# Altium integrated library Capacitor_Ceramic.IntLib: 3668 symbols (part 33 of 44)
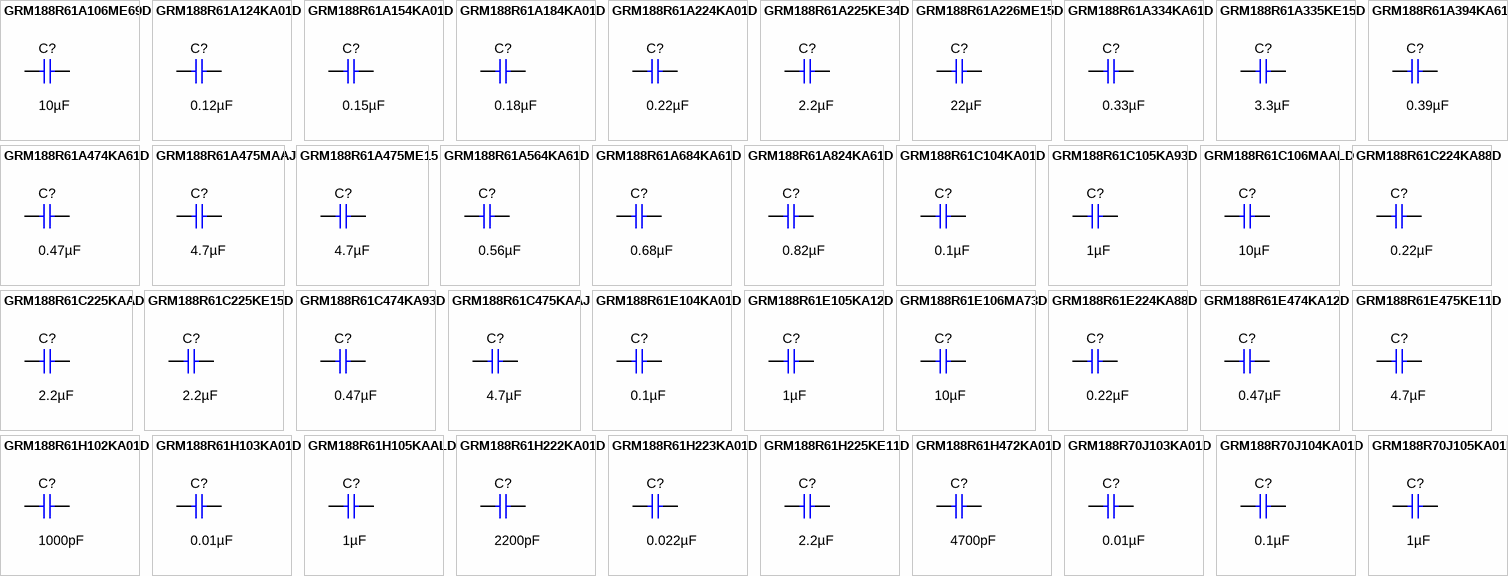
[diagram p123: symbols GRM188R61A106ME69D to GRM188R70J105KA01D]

## GRM188R61A224KA01D
designator C?  ValueDisplayed: 0.22µF  (hidden comment: GRM188R61A224KA01D)
CAP, CERM, 0.22 µF, 10 V,+/- 10%, X5R, 0603; Manufacturer: MuRata; Polarized: N; CompType: Capacitor; Value: 0.22uF; U/M: EA; Cap_F: 0.00000022; Tolerance_%: 10; Value2: 10V; TaMin_C: -55; TaMax_C: 85; Cap_Case: 0603; SizeArea_mm2: 1.28; SizeAreaWB_mm2: 4.68; SizeX_mm: 1.6; SizeY_mm: 0.8; SizeZ_mm: 1; AEC Category: Q200; Green_Lifecycle: Active; Green_REACh: Passed
signal-integrity model Cap
simulation model Cap
footprint 0603
footprint 0603M
footprint 0603L
footprint 0603_HV
footprint 0603S
pins: 1, 2

## GRM188R61A225KE34D
designator C?  ValueDisplayed: 2.2µF  (hidden comment: GRM188R61A225KE34D)
CAP, CERM, 2.2 µF, 10 V,+/- 10%, X5R, 0603; Manufacturer: MuRata; Polarized: N; CompType: Capacitor; Value: 2.2uF; U/M: EA; Cap_F: 0.0000022; Tolerance_%: 10; Value2: 10V; TaMin_C: -55; TaMax_C: 85; Cap_Case: 0603; SizeArea_mm2: 1.28; SizeAreaWB_mm2: 4.68; SizeX_mm: 1.6; SizeY_mm: 0.8; SizeZ_mm: 1; AEC Category: Q200; Green_Lifecycle: Active; Green_REACh: Passed
signal-integrity model Cap
simulation model Cap
footprint 0603
footprint 0603M
footprint 0603L
footprint 0603_HV
footprint 0603S
pins: 1, 2

## GRM188R61A226ME15D
designator C?  ValueDisplayed: 22µF  (hidden comment: GRM188R61A226ME15D)
CAP, CERM, 22 µF, 10 V,+/- 20%, X5R, 0603; Manufacturer: MuRata; Polarized: N; CompType: Capacitor; Value: 22uF; U/M: EA; Cap_F: 0.000022; Tolerance_%: 20; VDC_V: 10; Value2: 10V; TaMin_C: -55; TaMax_C: 85; Cap_Case: 0603; SizeArea_mm2: 1.28; SizeAreaWB_mm2: 4.68; SizeX_mm: 1.6; SizeY_mm: 0.8; SizeZ_mm: 1; AEC Category: Q200; Green_Lifecycle: Active; Green_REACh: Passed
signal-integrity model Cap
simulation model Cap
footprint 0603
footprint 0603M
footprint 0603L
footprint 0603_HV
footprint 0603S
pins: 1, 2

## GRM188R61A334KA61D
designator C?  ValueDisplayed: 0.33µF  (hidden comment: GRM188R61A334KA61D)
CAP, CERM, 0.33 µF, 10 V,+/- 10%, X5R, 0603; Manufacturer: MuRata; Polarized: N; CompType: Capacitor; Value: 0.33uF; U/M: EA; Cap_F: 0.00000033; Tolerance_%: 10; Value2: 10V; TaMin_C: -55; TaMax_C: 85; Cap_Case: 0603; SizeArea_mm2: 1.28; SizeAreaWB_mm2: 4.68; SizeX_mm: 1.6; SizeY_mm: 0.8; SizeZ_mm: 1; AEC Category: Q200
signal-integrity model Cap
simulation model Cap
footprint 0603
footprint 0603M
footprint 0603L
footprint 0603_HV
footprint 0603S
pins: 1, 2

## GRM188R61A335KE15D
designator C?  ValueDisplayed: 3.3µF  (hidden comment: GRM188R61A335KE15D)
CAP, CERM, 3.3 µF, 10 V,+/- 10%, X5R, 0603; Manufacturer: MuRata; Polarized: N; CompType: Capacitor; Value: 3.3uF; U/M: EA; Cap_F: 0.0000033; Tolerance_%: 10; ESR_ohm: 0.005; Value1: 0.005 ohm; Value2: 10V; IRMS_A: 1.7; TaMin_C: -55; TaMax_C: 85; Cap_Case: 0603; SizeArea_mm2: 1.28; SizeAreaWB_mm2: 4.68; SizeX_mm: 1.6; SizeY_mm: 0.8; SizeZ_mm: 1; AEC Category: Q200
signal-integrity model Cap
simulation model Cap
footprint 0603
footprint 0603M
footprint 0603L
footprint 0603_HV
footprint 0603S
pins: 1, 2

## GRM188R61A394KA61D
designator C?  ValueDisplayed: 0.39µF  (hidden comment: GRM188R61A394KA61D)
CAP, CERM, 0.39 µF, 10 V,+/- 10%, X5R, 0603; Manufacturer: MuRata; Polarized: N; CompType: Capacitor; Value: 0.39uF; U/M: EA; Cap_F: 0.00000039; Tolerance_%: 10; Value2: 10V; TaMin_C: -55; TaMax_C: 85; Cap_Case: 0603; SizeArea_mm2: 1.28; SizeAreaWB_mm2: 4.68; SizeX_mm: 1.6; SizeY_mm: 0.8; SizeZ_mm: 1; AEC Category: Q200
signal-integrity model Cap
simulation model Cap
footprint 0603
footprint 0603M
footprint 0603L
footprint 0603_HV
footprint 0603S
pins: 1, 2

## GRM188R61A474KA61D
designator C?  ValueDisplayed: 0.47µF  (hidden comment: GRM188R61A474KA61D)
CAP, CERM, 0.47 µF, 10 V,+/- 10%, X5R, 0603; Manufacturer: MuRata; Polarized: N; CompType: Capacitor; Value: 0.47uF; U/M: EA; Cap_F: 0.00000047; Tolerance_%: 10; Value2: 10V; TaMin_C: -55; TaMax_C: 85; Cap_Case: 0603; SizeArea_mm2: 1.28; SizeAreaWB_mm2: 4.68; SizeX_mm: 1.6; SizeY_mm: 0.8; SizeZ_mm: 1; AEC Category: Q200; Green_Lifecycle: Active; Green_REACh: Passed
signal-integrity model Cap
simulation model Cap
footprint 0603
footprint 0603M
footprint 0603L
footprint 0603_HV
footprint 0603S
pins: 1, 2

## GRM188R61A475MAAJ
designator C?  ValueDisplayed: 4.7µF  (hidden comment: GRM188R61A475MAAJ)
CAP, CERM, 4.7 µF, 10 V,+/- 20%, X5R, 0603; Manufacturer: MuRata; Polarized: N; CompType: Capacitor; Value: 4.7uF; U/M: EA; Cap_F: 0.0000047; Tolerance_%: 20; VDC_V: 10; Value2: 10V; TaMin_C: -55; TaMax_C: 85; Cap_Case: 0603; SizeArea_mm2: 1.28; SizeAreaWB_mm2: 4.68; SizeX_mm: 1.6; SizeY_mm: 0.8; SizeZ_mm: 1; AEC Category: Q200
signal-integrity model Cap
simulation model Cap
footprint 0603
footprint 0603M
footprint 0603L
footprint 0603_HV
footprint 0603S
pins: 1, 2

## GRM188R61A475ME15
designator C?  ValueDisplayed: 4.7µF  (hidden comment: GRM188R61A475ME15)
CAP, CERM, 4.7 µF, 10 V,+/- 20%, X5R, 0603; Manufacturer: MuRata; Polarized: N; CompType: Capacitor; Value: 4.7uF; U/M: EA; Cap_F: 0.0000047; Tolerance_%: 20; VDC_V: 10; Value2: 10V; TaMin_C: -55; TaMax_C: 85; Cap_Case: 0603; SizeArea_mm2: 1.28; SizeAreaWB_mm2: 4.68; SizeX_mm: 1.6; SizeY_mm: 0.8; SizeZ_mm: 1; AEC Category: Q200; Green_Lifecycle: Active; Green_REACh: Passed
signal-integrity model Cap
simulation model Cap
footprint 0603
footprint 0603M
footprint 0603L
footprint 0603_HV
footprint 0603S
pins: 1, 2

## GRM188R61A564KA61D
designator C?  ValueDisplayed: 0.56µF  (hidden comment: GRM188R61A564KA61D)
CAP, CERM, 0.56 µF, 10 V,+/- 10%, X5R, 0603; Manufacturer: MuRata; Polarized: N; CompType: Capacitor; Value: 0.56uF; U/M: EA; Cap_F: 0.00000056; Tolerance_%: 10; Value2: 10V; TaMin_C: -55; TaMax_C: 85; Cap_Case: 0603; SizeArea_mm2: 1.28; SizeAreaWB_mm2: 4.68; SizeX_mm: 1.6; SizeY_mm: 0.8; SizeZ_mm: 1; AEC Category: Q200
signal-integrity model Cap
simulation model Cap
footprint 0603
footprint 0603M
footprint 0603L
footprint 0603_HV
footprint 0603S
pins: 1, 2

## GRM188R61A684KA61D
designator C?  ValueDisplayed: 0.68µF  (hidden comment: GRM188R61A684KA61D)
CAP, CERM, 0.68 µF, 10 V,+/- 10%, X5R, 0603; Manufacturer: MuRata; Polarized: N; CompType: Capacitor; Value: 0.68uF; U/M: EA; Cap_F: 0.00000068; Tolerance_%: 10; Value2: 10V; TaMin_C: -55; TaMax_C: 85; Cap_Case: 0603; SizeArea_mm2: 1.28; SizeAreaWB_mm2: 4.68; SizeX_mm: 1.6; SizeY_mm: 0.8; SizeZ_mm: 1; AEC Category: Q200; Green_Lifecycle: Active; Green_REACh: Passed
signal-integrity model Cap
simulation model Cap
footprint 0603
footprint 0603M
footprint 0603L
footprint 0603_HV
footprint 0603S
pins: 1, 2

## GRM188R61A824KA61D
designator C?  ValueDisplayed: 0.82µF  (hidden comment: GRM188R61A824KA61D)
CAP, CERM, 0.82 µF, 10 V,+/- 10%, X5R, 0603; Manufacturer: MuRata; Polarized: N; CompType: Capacitor; Value: 0.82uF; U/M: EA; Cap_F: 0.00000082; Tolerance_%: 10; Value2: 10V; TaMin_C: -55; TaMax_C: 85; Cap_Case: 0603; SizeArea_mm2: 1.28; SizeAreaWB_mm2: 4.68; SizeX_mm: 1.6; SizeY_mm: 0.8; SizeZ_mm: 1; AEC Category: Q200
signal-integrity model Cap
simulation model Cap
footprint 0603
footprint 0603M
footprint 0603L
footprint 0603_HV
footprint 0603S
pins: 1, 2

## GRM188R61C104KA01D
designator C?  ValueDisplayed: 0.1µF  (hidden comment: GRM188R61C104KA01D)
CAP, CERM, 0.1 µF, 16 V,+/- 10%, X5R, 0603; Manufacturer: MuRata; Polarized: N; CompType: Capacitor; Value: 0.1uF; U/M: EA; Cap_F: 0.0000001; Tolerance_%: 10; VDC_V: 16; Value2: 16V; TaMin_C: -55; TaMax_C: 85; Cap_Case: 0603; SizeArea_mm2: 1.28; SizeAreaWB_mm2: 4.68; SizeX_mm: 1.6; SizeY_mm: 0.8; SizeZ_mm: 1; AEC Category: Q200; Green_Lifecycle: Active; Green_REACh: Passed
signal-integrity model Cap
simulation model Cap
footprint 0603
footprint 0603M
footprint 0603L
footprint 0603_HV
footprint 0603S
pins: 1, 2

## GRM188R61C105KA93D
designator C?  ValueDisplayed: 1µF  (hidden comment: GRM188R61C105KA93D)
CAP, CERM, 1 µF, 16 V,+/- 10%, X5R, 0603; Manufacturer: MuRata; Polarized: N; CompType: Capacitor; Value: 1uF; U/M: EA; Cap_F: 0.000001; Tolerance_%: 10; VDC_V: 16; Value2: 16V; TaMin_C: -55; TaMax_C: 85; Cap_Case: 0603; SizeArea_mm2: 1.28; SizeAreaWB_mm2: 4.68; SizeX_mm: 1.6; SizeY_mm: 0.8; SizeZ_mm: 1; AEC Category: Q200; Green_Lifecycle: Active; Green_REACh: Passed
signal-integrity model Cap
simulation model Cap
footprint 0603
footprint 0603M
footprint 0603L
footprint 0603_HV
footprint 0603S
pins: 1, 2

## GRM188R61C106MAALD
designator C?  ValueDisplayed: 10µF  (hidden comment: GRM188R61C106MAALD)
CAP, CERM, 10 µF, 16 V,+/- 20%, X5R, 0603; Manufacturer: MuRata; Polarized: N; CompType: Capacitor; Value: 10uF; U/M: EA; Cap_F: 0.00001; Tolerance_%: 20; VDC_V: 16; Value2: 16V; TaMin_C: -55; TaMax_C: 85; Cap_Case: 0603; SizeArea_mm2: 1.28; SizeAreaWB_mm2: 4.68; SizeX_mm: 1.6; SizeY_mm: 0.8; SizeZ_mm: 1; AEC Category: Q200; Green_Lifecycle: Active; Green_REACh: Passed
signal-integrity model Cap
simulation model Cap
footprint 0603
footprint 0603M
footprint 0603L
footprint 0603_HV
footprint 0603S
pins: 1, 2

## GRM188R61C224KA88D
designator C?  ValueDisplayed: 0.22µF  (hidden comment: GRM188R61C224KA88D)
CAP, CERM, 0.22 µF, 16 V,+/- 10%, X5R, 0603; Manufacturer: MuRata; Polarized: N; CompType: Capacitor; Value: 0.22uF; U/M: EA; Cap_F: 0.00000022; Tolerance_%: 10; VDC_V: 16; Value2: 16V; TaMin_C: -55; TaMax_C: 85; Cap_Case: 0603; SizeArea_mm2: 1.28; SizeAreaWB_mm2: 4.68; SizeX_mm: 1.6; SizeY_mm: 0.8; SizeZ_mm: 1; AEC Category: Q200; Green_Lifecycle: Active; Green_REACh: Passed
signal-integrity model Cap
simulation model Cap
footprint 0603
footprint 0603M
footprint 0603L
footprint 0603_HV
footprint 0603S
pins: 1, 2

## GRM188R61C225KAAD
designator C?  ValueDisplayed: 2.2µF  (hidden comment: GRM188R61C225KAAD)
CAP, CERM, 2.2 µF, 16 V,+/- 10%, X5R, 0603; Manufacturer: MuRata; Polarized: N; CompType: Capacitor; Value: 2.2uF; U/M: EA; Cap_F: 0.0000022; Tolerance_%: 10; VDC_V: 16; Value2: 16V; TaMin_C: -55; TaMax_C: 85; Cap_Case: 0603; SizeArea_mm2: 1.28; SizeAreaWB_mm2: 4.68; SizeX_mm: 1.6; SizeY_mm: 0.8; SizeZ_mm: 1; AEC Category: Q200; Green_Lifecycle: Not Set; Green_REACh: Incomplete
signal-integrity model Cap
simulation model Cap
footprint 0603
footprint 0603M
footprint 0603L
footprint 0603_HV
footprint 0603S
pins: 1, 2

## GRM188R61C225KE15D
designator C?  ValueDisplayed: 2.2µF  (hidden comment: GRM188R61C225KE15D)
CAP, CERM, 2.2 µF, 16 V,+/- 10%, X5R, 0603; Manufacturer: MuRata; Polarized: N; CompType: Capacitor; Value: 2.2uF; U/M: EA; Cap_F: 0.0000022; Tolerance_%: 10; VDC_V: 16; Value2: 16V; TaMin_C: -55; TaMax_C: 85; Cap_Case: 0603; SizeArea_mm2: 1.28; SizeAreaWB_mm2: 4.68; SizeX_mm: 1.6; SizeY_mm: 0.8; SizeZ_mm: 1; AEC Category: Q200; Green_Lifecycle: Active; Green_REACh: Passed
signal-integrity model Cap
simulation model Cap
footprint 0603
footprint 0603M
footprint 0603L
footprint 0603_HV
footprint 0603S
pins: 1, 2

## GRM188R61C474KA93D
designator C?  ValueDisplayed: 0.47µF  (hidden comment: GRM188R61C474KA93D)
CAP, CERM, 0.47 µF, 16 V,+/- 10%, X5R, 0603; Manufacturer: MuRata; Polarized: N; CompType: Capacitor; Value: 0.47uF; U/M: EA; Cap_F: 0.00000047; Tolerance_%: 10; VDC_V: 16; Value2: 16V; TaMin_C: -55; TaMax_C: 85; Cap_Case: 0603; SizeArea_mm2: 1.28; SizeAreaWB_mm2: 4.68; SizeX_mm: 1.6; SizeY_mm: 0.8; SizeZ_mm: 1; AEC Category: Q200; Green_Lifecycle: Active; Green_REACh: Passed
signal-integrity model Cap
simulation model Cap
footprint 0603
footprint 0603M
footprint 0603L
footprint 0603_HV
footprint 0603S
pins: 1, 2

## GRM188R61C475KAAJ
designator C?  ValueDisplayed: 4.7µF  (hidden comment: GRM188R61C475KAAJ)
CAP, CERM, 4.7 µF, 16 V,+/- 10%, X5R, 0603; Manufacturer: MuRata; Polarized: N; CompType: Capacitor; Value: 4.7uF; U/M: EA; Cap_F: 0.0000047; Tolerance_%: 10; VDC_V: 16; Value2: 16V; TaMin_C: -55; TaMax_C: 85; Cap_Case: 0603; SizeArea_mm2: 1.28; SizeAreaWB_mm2: 4.68; SizeX_mm: 1.6; SizeY_mm: 0.8; SizeZ_mm: 1; AEC Category: Q200; Green_Lifecycle: Active; Green_REACh: Passed
signal-integrity model Cap
simulation model Cap
footprint 0603
footprint 0603M
footprint 0603L
footprint 0603_HV
footprint 0603S
pins: 1, 2

## GRM188R61E104KA01D
designator C?  ValueDisplayed: 0.1µF  (hidden comment: GRM188R61E104KA01D)
CAP, CERM, 0.1 µF, 25 V,+/- 10%, X5R, 0603; Manufacturer: MuRata; Polarized: N; CompType: Capacitor; Value: 0.1uF; U/M: EA; Cap_F: 0.0000001; Tolerance_%: 10; VDC_V: 25; Value2: 25V; TaMin_C: -55; TaMax_C: 85; Cap_Case: 0603; SizeArea_mm2: 1.28; SizeAreaWB_mm2: 4.68; SizeX_mm: 1.6; SizeY_mm: 0.8; SizeZ_mm: 1; AEC Category: Q200; Green_Lifecycle: Active; Green_REACh: Passed
signal-integrity model Cap
simulation model Cap
footprint 0603
footprint 0603M
footprint 0603L
footprint 0603_HV
footprint 0603S
pins: 1, 2

## GRM188R61E105KA12D
designator C?  ValueDisplayed: 1µF  (hidden comment: GRM188R61E105KA12D)
CAP, CERM, 1 µF, 25 V,+/- 10%, X5R, 0603; Manufacturer: MuRata; Polarized: N; CompType: Capacitor; Value: 1uF; U/M: EA; Cap_F: 0.000001; Tolerance_%: 10; VDC_V: 25; Value2: 25V; TaMin_C: -55; TaMax_C: 85; Cap_Case: 0603; SizeArea_mm2: 1.28; SizeAreaWB_mm2: 4.68; SizeX_mm: 1.6; SizeY_mm: 0.8; SizeZ_mm: 1; AEC Category: Q200; Green_Lifecycle: Active; Green_REACh: Passed
signal-integrity model Cap
simulation model Cap
footprint 0603
footprint 0603M
footprint 0603L
footprint 0603_HV
footprint 0603S
pins: 1, 2

## GRM188R61E106MA73D
designator C?  ValueDisplayed: 10µF  (hidden comment: GRM188R61E106MA73D)
CAP, CERM, 10 µF, 25 V,+/- 20%, X5R, 0603; Manufacturer: MuRata; Polarized: N; CompType: Capacitor; Value: 10uF; U/M: EA; Cap_F: 0.00001; Tolerance_%: 20; VDC_V: 25; Value2: 25V; TaMin_C: -55; TaMax_C: 85; Cap_Case: 0603; SizeArea_mm2: 1.28; SizeAreaWB_mm2: 4.68; SizeX_mm: 1.6; SizeY_mm: 0.8; SizeZ_mm: 1; AEC Category: Q200; Green_Lifecycle: Active; Green_REACh: Passed
signal-integrity model Cap
simulation model Cap
footprint 0603
footprint 0603M
footprint 0603L
footprint 0603_HV
footprint 0603S
pins: 1, 2

## GRM188R61E224KA88D
designator C?  ValueDisplayed: 0.22µF  (hidden comment: GRM188R61E224KA88D)
CAP, CERM, 0.22 µF, 25 V,+/- 10%, X5R, 0603; Manufacturer: MuRata; Polarized: N; CompType: Capacitor; Value: 0.22uF; U/M: EA; Cap_F: 0.00000022; Tolerance_%: 10; VDC_V: 25; Value2: 25V; TaMin_C: -55; TaMax_C: 85; Cap_Case: 0603; SizeArea_mm2: 1.28; SizeAreaWB_mm2: 4.68; SizeX_mm: 1.6; SizeY_mm: 0.8; SizeZ_mm: 1; AEC Category: Q200; Green_Lifecycle: Active; Green_REACh: Passed
signal-integrity model Cap
simulation model Cap
footprint 0603
footprint 0603M
footprint 0603L
footprint 0603_HV
footprint 0603S
pins: 1, 2

## GRM188R61E474KA12D
designator C?  ValueDisplayed: 0.47µF  (hidden comment: GRM188R61E474KA12D)
CAP, CERM, 0.47 µF, 25 V,+/- 10%, X5R, 0603; Manufacturer: MuRata; Polarized: N; CompType: Capacitor; Value: 0.47uF; U/M: EA; Cap_F: 0.00000047; Tolerance_%: 10; VDC_V: 25; Value2: 25V; TaMin_C: -55; TaMax_C: 85; Cap_Case: 0603; SizeArea_mm2: 1.28; SizeAreaWB_mm2: 4.68; SizeX_mm: 1.6; SizeY_mm: 0.8; SizeZ_mm: 1; AEC Category: Q200; Green_Lifecycle: Active; Green_REACh: Passed
signal-integrity model Cap
simulation model Cap
footprint 0603
footprint 0603M
footprint 0603L
footprint 0603_HV
footprint 0603S
pins: 1, 2

## GRM188R61E475KE11D
designator C?  ValueDisplayed: 4.7µF  (hidden comment: GRM188R61E475KE11D)
CAP, CERM, 4.7 µF, 25 V,+/- 10%, X5R, 0603; Manufacturer: MuRata; Polarized: N; CompType: Capacitor; Value: 4.7uF; U/M: EA; Cap_F: 0.0000047; Tolerance_%: 10; VDC_V: 25; Value2: 25V; TaMin_C: -55; TaMax_C: 85; Cap_Case: 0603; SizeArea_mm2: 1.28; SizeAreaWB_mm2: 4.68; SizeX_mm: 1.6; SizeY_mm: 0.8; SizeZ_mm: 1; AEC Category: Q200; Green_Lifecycle: Active; Green_REACh: Passed
signal-integrity model Cap
simulation model Cap
footprint 0603
footprint 0603M
footprint 0603L
footprint 0603_HV
footprint 0603S
pins: 1, 2

## GRM188R61H102KA01D
designator C?  ValueDisplayed: 1000pF  (hidden comment: GRM188R61H102KA01D)
CAP, CERM, 1000 pF, 50 V,+/- 10%, X5R, 0603; Manufacturer: MuRata; Polarized: N; CompType: Capacitor; Value: 1000pF; U/M: EA; Cap_F: 0.000000001; Tolerance_%: 10; VDC_V: 50; Value2: 50V; TaMin_C: -55; TaMax_C: 85; Cap_Case: 0603; SizeArea_mm2: 1.28; SizeAreaWB_mm2: 4.68; SizeX_mm: 1.6; SizeY_mm: 0.8; SizeZ_mm: 1; AEC Category: Q200; Green_Lifecycle: Active; Green_REACh: Passed
signal-integrity model Cap
simulation model Cap
footprint 0603
footprint 0603M
footprint 0603L
footprint 0603_HV
footprint 0603S
pins: 1, 2

## GRM188R61H103KA01D
designator C?  ValueDisplayed: 0.01µF  (hidden comment: GRM188R61H103KA01D)
CAP, CERM, 0.01 µF, 50 V,+/- 10%, X5R, 0603; Manufacturer: MuRata; Polarized: N; CompType: Capacitor; Value: 0.01uF; U/M: EA; Cap_F: 0.00000001; Tolerance_%: 10; VDC_V: 50; Value2: 50V; TaMin_C: -55; TaMax_C: 85; Cap_Case: 0603; SizeArea_mm2: 1.28; SizeAreaWB_mm2: 4.68; SizeX_mm: 1.6; SizeY_mm: 0.8; SizeZ_mm: 1; AEC Category: Q200; Green_Lifecycle: Active; Green_REACh: Passed
signal-integrity model Cap
simulation model Cap
footprint 0603
footprint 0603M
footprint 0603L
footprint 0603_HV
footprint 0603S
pins: 1, 2

## GRM188R61H105KAALD
designator C?  ValueDisplayed: 1µF  (hidden comment: GRM188R61H105KAALD)
CAP, CERM, 1 µF, 50 V,+/- 10%, X5R, 0603; Manufacturer: MuRata; Polarized: N; CompType: Capacitor; Value: 1uF; U/M: EA; Cap_F: 0.000001; Tolerance_%: 10; VDC_V: 50; Value2: 50V; TaMin_C: -55; TaMax_C: 85; Cap_Case: 0603; SizeArea_mm2: 1.28; SizeAreaWB_mm2: 4.68; SizeX_mm: 1.6; SizeY_mm: 0.8; SizeZ_mm: 1; AEC Category: Q200; Green_Lifecycle: Active; Green_REACh: Passed
signal-integrity model Cap
simulation model Cap
footprint 0603
footprint 0603M
footprint 0603L
footprint 0603_HV
footprint 0603S
pins: 1, 2

## GRM188R61H222KA01D
designator C?  ValueDisplayed: 2200pF  (hidden comment: GRM188R61H222KA01D)
CAP, CERM, 2200 pF, 50 V,+/- 10%, X5R, 0603; Manufacturer: MuRata; Polarized: N; CompType: Capacitor; Value: 2200pF; U/M: EA; Cap_F: 0.0000000022; Tolerance_%: 10; VDC_V: 50; Value2: 50V; TaMin_C: -55; TaMax_C: 85; Cap_Case: 0603; SizeArea_mm2: 1.28; SizeAreaWB_mm2: 4.68; SizeX_mm: 1.6; SizeY_mm: 0.8; SizeZ_mm: 1; AEC Category: Q200
signal-integrity model Cap
simulation model Cap
footprint 0603
footprint 0603M
footprint 0603L
footprint 0603_HV
footprint 0603S
pins: 1, 2

## GRM188R61H223KA01D
designator C?  ValueDisplayed: 0.022µF  (hidden comment: GRM188R61H223KA01D)
CAP, CERM, 0.022 µF, 50 V,+/- 10%, X5R, 0603; Manufacturer: MuRata; Polarized: N; CompType: Capacitor; Value: 0.022uF; U/M: EA; Cap_F: 0.000000022; Tolerance_%: 10; VDC_V: 50; Value2: 50V; TaMin_C: -55; TaMax_C: 85; Cap_Case: 0603; SizeArea_mm2: 1.28; SizeAreaWB_mm2: 4.68; SizeX_mm: 1.6; SizeY_mm: 0.8; SizeZ_mm: 1; AEC Category: Q200
signal-integrity model Cap
simulation model Cap
footprint 0603
footprint 0603M
footprint 0603L
footprint 0603_HV
footprint 0603S
pins: 1, 2

## GRM188R61H225KE11D
designator C?  ValueDisplayed: 2.2µF  (hidden comment: GRM188R61H225KE11D)
CAP, CERM, 2.2 µF, 50 V,+/- 10%, X5R, 0603; Manufacturer: MuRata; Polarized: N; CompType: Capacitor; Value: 2.2uF; U/M: EA; Cap_F: 0.0000022; Tolerance_%: 10; VDC_V: 50; Value2: 50V; TaMin_C: -55; TaMax_C: 85; Cap_Case: 0603; SizeArea_mm2: 1.28; SizeAreaWB_mm2: 4.68; SizeX_mm: 1.6; SizeY_mm: 0.8; SizeZ_mm: 1; AEC Category: Q200
signal-integrity model Cap
simulation model Cap
footprint 0603
footprint 0603M
footprint 0603L
footprint 0603_HV
footprint 0603S
pins: 1, 2

## GRM188R61H472KA01D
designator C?  ValueDisplayed: 4700pF  (hidden comment: GRM188R61H472KA01D)
CAP, CERM, 4700 pF, 50 V,+/- 10%, X5R, 0603; Manufacturer: MuRata; Polarized: N; CompType: Capacitor; Value: 4700pF; U/M: EA; Cap_F: 0.0000000047; Tolerance_%: 10; VDC_V: 50; Value2: 50V; TaMin_C: -55; TaMax_C: 85; Cap_Case: 0603; SizeArea_mm2: 1.28; SizeAreaWB_mm2: 4.68; SizeX_mm: 1.6; SizeY_mm: 0.8; SizeZ_mm: 1; AEC Category: Q200; Green_Lifecycle: Active; Green_REACh: Passed
signal-integrity model Cap
simulation model Cap
footprint 0603
footprint 0603M
footprint 0603L
footprint 0603_HV
footprint 0603S
pins: 1, 2

## GRM188R70J103KA01D
designator C?  ValueDisplayed: 0.01µF  (hidden comment: GRM188R70J103KA01D)
CAP, CERM, 0.01 µF, 6.3 V,+/- 10%, X7R, 0603; Manufacturer: MuRata; Polarized: N; CompType: Capacitor; Value: 0.01uF; U/M: EA; Cap_F: 0.00000001; Tolerance_%: 10; VDC_V: 6.3; Value2: 6.3V; TaMin_C: -55; TaMax_C: 125; Cap_Case: 0603; SizeArea_mm2: 1.28; SizeAreaWB_mm2: 4.68; SizeX_mm: 1.6; SizeY_mm: 0.8; SizeZ_mm: 1; AEC Category: Q200; Green_Lifecycle: Active; Green_REACh: Passed
signal-integrity model Cap
simulation model Cap
footprint 0603
footprint 0603M
footprint 0603L
footprint 0603_HV
footprint 0603S
pins: 1, 2

## GRM188R70J104KA01D
designator C?  ValueDisplayed: 0.1µF  (hidden comment: GRM188R70J104KA01D)
CAP, CERM, 0.1 µF, 6.3 V,+/- 10%, X7R, 0603; Manufacturer: MuRata; Polarized: N; CompType: Capacitor; Value: 0.1uF; U/M: EA; Cap_F: 0.0000001; Tolerance_%: 10; VDC_V: 6.3; Value2: 6.3V; TaMin_C: -55; TaMax_C: 125; Cap_Case: 0603; SizeArea_mm2: 1.28; SizeAreaWB_mm2: 4.68; SizeX_mm: 1.6; SizeY_mm: 0.8; SizeZ_mm: 1; AEC Category: Q200; Green_Lifecycle: Active; Green_REACh: Passed
signal-integrity model Cap
simulation model Cap
footprint 0603
footprint 0603M
footprint 0603L
footprint 0603_HV
footprint 0603S
pins: 1, 2

## GRM188R70J105KA01D
designator C?  ValueDisplayed: 1µF  (hidden comment: GRM188R70J105KA01D)
CAP, CERM, 1 µF, 6.3 V,+/- 10%, X7R, 0603; Manufacturer: MuRata; Polarized: N; CompType: Capacitor; Value: 1uF; U/M: EA; Cap_F: 0.000001; Tolerance_%: 10; VDC_V: 6.3; Value2: 6.3V; TaMin_C: -55; TaMax_C: 125; Cap_Case: 0603; SizeArea_mm2: 1.28; SizeAreaWB_mm2: 4.68; SizeX_mm: 1.6; SizeY_mm: 0.8; SizeZ_mm: 1; AEC Category: Q200; Green_Lifecycle: Active; Green_REACh: Passed
signal-integrity model Cap
simulation model Cap
footprint 0603
footprint 0603M
footprint 0603L
footprint 0603_HV
footprint 0603S
pins: 1, 2

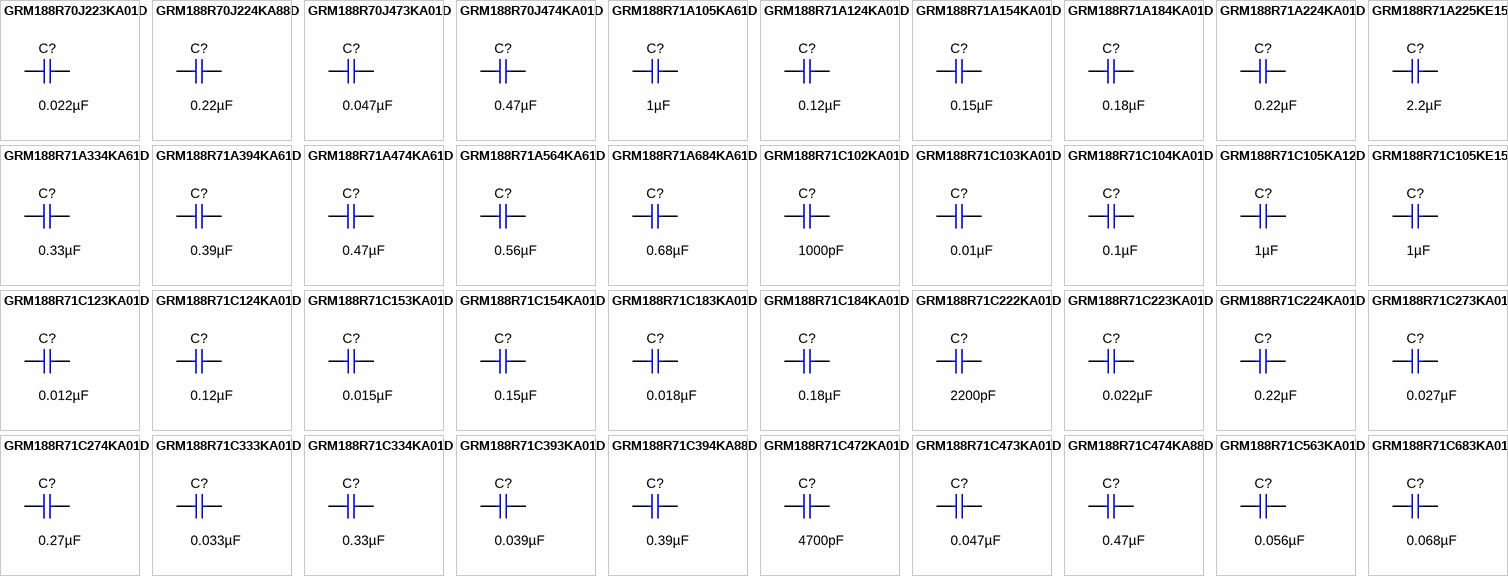
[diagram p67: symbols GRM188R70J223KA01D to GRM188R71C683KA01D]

## GRM188R70J223KA01D
designator C?  ValueDisplayed: 0.022µF  (hidden comment: GRM188R70J223KA01D)
CAP, CERM, 0.022 µF, 6.3 V,+/- 10%, X7R, 0603; Manufacturer: MuRata; Polarized: N; CompType: Capacitor; Value: 0.022uF; U/M: EA; Cap_F: 0.000000022; Tolerance_%: 10; VDC_V: 6.3; Value2: 6.3V; TaMin_C: -55; TaMax_C: 125; Cap_Case: 0603; SizeArea_mm2: 1.28; SizeAreaWB_mm2: 4.68; SizeX_mm: 1.6; SizeY_mm: 0.8; SizeZ_mm: 1; AEC Category: Q200
signal-integrity model Cap
simulation model Cap
footprint 0603
footprint 0603M
footprint 0603L
footprint 0603_HV
footprint 0603S
pins: 1, 2

## GRM188R70J224KA88D
designator C?  ValueDisplayed: 0.22µF  (hidden comment: GRM188R70J224KA88D)
CAP, CERM, 0.22 µF, 6.3 V,+/- 10%, X7R, 0603; Manufacturer: MuRata; Polarized: N; CompType: Capacitor; Value: 0.22uF; U/M: EA; Cap_F: 0.00000022; Tolerance_%: 10; VDC_V: 6.3; Value2: 6.3V; TaMin_C: -55; TaMax_C: 125; Cap_Case: 0603; SizeArea_mm2: 1.28; SizeAreaWB_mm2: 4.68; SizeX_mm: 1.6; SizeY_mm: 0.8; SizeZ_mm: 1; AEC Category: Q200
signal-integrity model Cap
simulation model Cap
footprint 0603
footprint 0603M
footprint 0603L
footprint 0603_HV
footprint 0603S
pins: 1, 2

## GRM188R70J473KA01D
designator C?  ValueDisplayed: 0.047µF  (hidden comment: GRM188R70J473KA01D)
CAP, CERM, 0.047 µF, 6.3 V,+/- 10%, X7R, 0603; Manufacturer: MuRata; Polarized: N; CompType: Capacitor; Value: 0.047uF; U/M: EA; Cap_F: 0.000000047; Tolerance_%: 10; VDC_V: 6.3; Value2: 6.3V; TaMin_C: -55; TaMax_C: 125; Cap_Case: 0603; SizeArea_mm2: 1.28; SizeAreaWB_mm2: 4.68; SizeX_mm: 1.6; SizeY_mm: 0.8; SizeZ_mm: 1; AEC Category: Q200
signal-integrity model Cap
simulation model Cap
footprint 0603
footprint 0603M
footprint 0603L
footprint 0603_HV
footprint 0603S
pins: 1, 2

## GRM188R70J474KA01D
designator C?  ValueDisplayed: 0.47µF  (hidden comment: GRM188R70J474KA01D)
CAP, CERM, 0.47 µF, 6.3 V,+/- 10%, X7R, 0603; Manufacturer: MuRata; Polarized: N; CompType: Capacitor; Value: 0.47uF; U/M: EA; Cap_F: 0.00000047; Tolerance_%: 10; VDC_V: 6.3; Value2: 6.3V; TaMin_C: -55; TaMax_C: 125; Cap_Case: 0603; SizeArea_mm2: 1.28; SizeAreaWB_mm2: 4.68; SizeX_mm: 1.6; SizeY_mm: 0.8; SizeZ_mm: 1; AEC Category: Q200
signal-integrity model Cap
simulation model Cap
footprint 0603
footprint 0603M
footprint 0603L
footprint 0603_HV
footprint 0603S
pins: 1, 2

## GRM188R71A105KA61D
designator C?  ValueDisplayed: 1µF  (hidden comment: GRM188R71A105KA61D)
CAP, CERM, 1 µF, 10 V,+/- 10%, X7R, 0603; Manufacturer: MuRata; Polarized: N; CompType: Capacitor; Value: 1uF; U/M: EA; Cap_F: 0.000001; Tolerance_%: 10; ESR_ohm: 0.011; Value1: 0.011 ohm; Value2: 10V; TaMin_C: -55; TaMax_C: 125; Cap_Case: 0603; SizeArea_mm2: 1.28; SizeAreaWB_mm2: 4.68; SizeX_mm: 1.6; SizeY_mm: 0.8; SizeZ_mm: 1; AEC Category: Q200; Green_Lifecycle: Active; Green_REACh: Passed
signal-integrity model Cap
simulation model Cap
footprint 0603
footprint 0603M
footprint 0603L
footprint 0603_HV
footprint 0603S
pins: 1, 2

## GRM188R71A124KA01D
designator C?  ValueDisplayed: 0.12µF  (hidden comment: GRM188R71A124KA01D)
CAP, CERM, 0.12 µF, 10 V,+/- 10%, X7R, 0603; Manufacturer: MuRata; Polarized: N; CompType: Capacitor; Value: 0.12uF; U/M: EA; Cap_F: 0.00000012; Tolerance_%: 10; Value2: 10V; TaMin_C: -55; TaMax_C: 125; Cap_Case: 0603; SizeArea_mm2: 1.28; SizeAreaWB_mm2: 4.68; SizeX_mm: 1.6; SizeY_mm: 0.8; SizeZ_mm: 1; AEC Category: Q200
signal-integrity model Cap
simulation model Cap
footprint 0603
footprint 0603M
footprint 0603L
footprint 0603_HV
footprint 0603S
pins: 1, 2

## GRM188R71A154KA01D
designator C?  ValueDisplayed: 0.15µF  (hidden comment: GRM188R71A154KA01D)
CAP, CERM, 0.15 µF, 10 V,+/- 10%, X7R, 0603; Manufacturer: MuRata; Polarized: N; CompType: Capacitor; Value: 0.15uF; U/M: EA; Cap_F: 0.00000015; Tolerance_%: 10; Value2: 10V; TaMin_C: -55; TaMax_C: 125; Cap_Case: 0603; SizeArea_mm2: 1.28; SizeAreaWB_mm2: 4.68; SizeX_mm: 1.6; SizeY_mm: 0.8; SizeZ_mm: 1; AEC Category: Q200; Green_Lifecycle: Active; Green_REACh: Passed
signal-integrity model Cap
simulation model Cap
footprint 0603
footprint 0603M
footprint 0603L
footprint 0603_HV
footprint 0603S
pins: 1, 2

## GRM188R71A184KA01D
designator C?  ValueDisplayed: 0.18µF  (hidden comment: GRM188R71A184KA01D)
CAP, CERM, 0.18 µF, 10 V,+/- 10%, X7R, 0603; Manufacturer: MuRata; Polarized: N; CompType: Capacitor; Value: 0.18uF; U/M: EA; Cap_F: 0.00000018; Tolerance_%: 10; Value2: 10V; TaMin_C: -55; TaMax_C: 125; Cap_Case: 0603; SizeArea_mm2: 1.28; SizeAreaWB_mm2: 4.68; SizeX_mm: 1.6; SizeY_mm: 0.8; SizeZ_mm: 1; AEC Category: Q200
signal-integrity model Cap
simulation model Cap
footprint 0603
footprint 0603M
footprint 0603L
footprint 0603_HV
footprint 0603S
pins: 1, 2

## GRM188R71A224KA01D
designator C?  ValueDisplayed: 0.22µF  (hidden comment: GRM188R71A224KA01D)
CAP, CERM, 0.22 µF, 10 V,+/- 10%, X7R, 0603; Manufacturer: MuRata; Polarized: N; CompType: Capacitor; Value: 0.22uF; U/M: EA; Cap_F: 0.00000022; Tolerance_%: 10; Value2: 10V; TaMin_C: -55; TaMax_C: 125; Cap_Case: 0603; SizeArea_mm2: 1.28; SizeAreaWB_mm2: 4.68; SizeX_mm: 1.6; SizeY_mm: 0.8; SizeZ_mm: 1; AEC Category: Q200; Green_Lifecycle: Active; Green_REACh: Passed
signal-integrity model Cap
simulation model Cap
footprint 0603
footprint 0603M
footprint 0603L
footprint 0603_HV
footprint 0603S
pins: 1, 2

## GRM188R71A225KE15D
designator C?  ValueDisplayed: 2.2µF  (hidden comment: GRM188R71A225KE15D)
CAP, CERM, 2.2 µF, 10 V,+/- 10%, X7R, 0603; Manufacturer: MuRata; Polarized: N; CompType: Capacitor; Value: 2.2uF; U/M: EA; Cap_F: 0.0000022; Tolerance_%: 10; ESR_ohm: 0.009; Value1: 0.009 ohm; Value2: 10V; TaMin_C: -55; TaMax_C: 125; Cap_Case: 0603; SizeArea_mm2: 1.28; SizeAreaWB_mm2: 4.68; SizeX_mm: 1.6; SizeY_mm: 0.8; SizeZ_mm: 1; AEC Category: Q200; Green_Lifecycle: Active; Green_REACh: Passed
signal-integrity model Cap
simulation model Cap
footprint 0603
footprint 0603M
footprint 0603L
footprint 0603_HV
footprint 0603S
pins: 1, 2

## GRM188R71A334KA61D
designator C?  ValueDisplayed: 0.33µF  (hidden comment: GRM188R71A334KA61D)
CAP, CERM, 0.33 µF, 10 V,+/- 10%, X7R, 0603; Manufacturer: MuRata; Polarized: N; CompType: Capacitor; Value: 0.33uF; U/M: EA; Cap_F: 0.00000033; Tolerance_%: 10; Value2: 10V; TaMin_C: -55; TaMax_C: 125; Cap_Case: 0603; SizeArea_mm2: 1.28; SizeAreaWB_mm2: 4.68; SizeX_mm: 1.6; SizeY_mm: 0.8; SizeZ_mm: 1; AEC Category: Q200; Green_Lifecycle: Active; Green_REACh: Passed
signal-integrity model Cap
simulation model Cap
footprint 0603
footprint 0603M
footprint 0603L
footprint 0603_HV
footprint 0603S
pins: 1, 2

## GRM188R71A394KA61D
designator C?  ValueDisplayed: 0.39µF  (hidden comment: GRM188R71A394KA61D)
CAP, CERM, 0.39 µF, 10 V,+/- 10%, X7R, 0603; Manufacturer: MuRata; Polarized: N; CompType: Capacitor; Value: 0.39uF; U/M: EA; Cap_F: 0.00000039; Tolerance_%: 10; Value2: 10V; TaMin_C: -55; TaMax_C: 125; Cap_Case: 0603; SizeArea_mm2: 1.28; SizeAreaWB_mm2: 4.68; SizeX_mm: 1.6; SizeY_mm: 0.8; SizeZ_mm: 1; AEC Category: Q200
signal-integrity model Cap
simulation model Cap
footprint 0603
footprint 0603M
footprint 0603L
footprint 0603_HV
footprint 0603S
pins: 1, 2

## GRM188R71A474KA61D
designator C?  ValueDisplayed: 0.47µF  (hidden comment: GRM188R71A474KA61D)
CAP, CERM, 0.47 µF, 10 V,+/- 10%, X7R, 0603; Manufacturer: MuRata; Polarized: N; CompType: Capacitor; Value: 0.47uF; U/M: EA; Cap_F: 0.00000047; Tolerance_%: 10; Value2: 10V; TaMin_C: -55; TaMax_C: 125; Cap_Case: 0603; SizeArea_mm2: 1.28; SizeAreaWB_mm2: 4.68; SizeX_mm: 1.6; SizeY_mm: 0.8; SizeZ_mm: 1; AEC Category: Q200; Green_Lifecycle: Active; Green_REACh: Passed
signal-integrity model Cap
simulation model Cap
footprint 0603
footprint 0603M
footprint 0603L
footprint 0603_HV
footprint 0603S
pins: 1, 2

## GRM188R71A564KA61D
designator C?  ValueDisplayed: 0.56µF  (hidden comment: GRM188R71A564KA61D)
CAP, CERM, 0.56 µF, 10 V,+/- 10%, X7R, 0603; Manufacturer: MuRata; Polarized: N; CompType: Capacitor; Value: 0.56uF; U/M: EA; Cap_F: 0.00000056; Tolerance_%: 10; Value2: 10V; TaMin_C: -55; TaMax_C: 125; Cap_Case: 0603; SizeArea_mm2: 1.28; SizeAreaWB_mm2: 4.68; SizeX_mm: 1.6; SizeY_mm: 0.8; SizeZ_mm: 1; AEC Category: Q200
signal-integrity model Cap
simulation model Cap
footprint 0603
footprint 0603M
footprint 0603L
footprint 0603_HV
footprint 0603S
pins: 1, 2

## GRM188R71A684KA61D
designator C?  ValueDisplayed: 0.68µF  (hidden comment: GRM188R71A684KA61D)
CAP, CERM, 0.68 µF, 10 V,+/- 10%, X7R, 0603; Manufacturer: MuRata; Polarized: N; CompType: Capacitor; Value: 0.68uF; U/M: EA; Cap_F: 0.00000068; Tolerance_%: 10; Value2: 10V; TaMin_C: -55; TaMax_C: 125; Cap_Case: 0603; SizeArea_mm2: 1.28; SizeAreaWB_mm2: 4.68; SizeX_mm: 1.6; SizeY_mm: 0.8; SizeZ_mm: 1; AEC Category: Q200; Green_Lifecycle: Active; Green_REACh: Passed
signal-integrity model Cap
simulation model Cap
footprint 0603
footprint 0603M
footprint 0603L
footprint 0603_HV
footprint 0603S
pins: 1, 2

## GRM188R71C102KA01D
designator C?  ValueDisplayed: 1000pF  (hidden comment: GRM188R71C102KA01D)
CAP, CERM, 1000 pF, 16 V,+/- 10%, X7R, 0603; Manufacturer: MuRata; Polarized: N; CompType: Capacitor; Value: 1000pF; U/M: EA; Cap_F: 0.000000001; Tolerance_%: 10; VDC_V: 16; Value2: 16V; TaMin_C: -55; TaMax_C: 125; Cap_Case: 0603; SizeArea_mm2: 1.28; SizeAreaWB_mm2: 4.68; SizeX_mm: 1.6; SizeY_mm: 0.8; SizeZ_mm: 1; AEC Category: Q200; Green_Lifecycle: Active; Green_REACh: Passed
signal-integrity model Cap
simulation model Cap
footprint 0603
footprint 0603M
footprint 0603L
footprint 0603_HV
footprint 0603S
pins: 1, 2

## GRM188R71C103KA01D
designator C?  ValueDisplayed: 0.01µF  (hidden comment: GRM188R71C103KA01D)
CAP, CERM, 0.01 µF, 16 V,+/- 10%, X7R, 0603; Manufacturer: MuRata; Polarized: N; CompType: Capacitor; Value: 0.01uF; U/M: EA; Cap_F: 0.00000001; Tolerance_%: 10; VDC_V: 16; Value2: 16V; TaMin_C: -55; TaMax_C: 125; Cap_Case: 0603; SizeArea_mm2: 1.28; SizeAreaWB_mm2: 4.68; SizeX_mm: 1.6; SizeY_mm: 0.8; SizeZ_mm: 1; AEC Category: Q200; Green_Lifecycle: Active; Green_REACh: Passed
signal-integrity model Cap
simulation model Cap
footprint 0603
footprint 0603M
footprint 0603L
footprint 0603_HV
footprint 0603S
pins: 1, 2

## GRM188R71C104KA01D
designator C?  ValueDisplayed: 0.1µF  (hidden comment: GRM188R71C104KA01D)
CAP, CERM, 0.1 µF, 16 V,+/- 10%, X7R, 0603; Manufacturer: MuRata; Polarized: N; CompType: Capacitor; Value: 0.1uF; U/M: EA; Cap_F: 0.0000001; Tolerance_%: 10; VDC_V: 16; Value2: 16V; TaMin_C: -55; TaMax_C: 125; Cap_Case: 0603; SizeArea_mm2: 1.28; SizeAreaWB_mm2: 4.68; SizeX_mm: 1.6; SizeY_mm: 0.8; SizeZ_mm: 1; AEC Category: Q200; Green_Lifecycle: Active; Green_REACh: Passed
signal-integrity model Cap
simulation model Cap
footprint 0603
footprint 0603M
footprint 0603L
footprint 0603_HV
footprint 0603S
pins: 1, 2

## GRM188R71C105KA12D
designator C?  ValueDisplayed: 1µF  (hidden comment: GRM188R71C105KA12D)
CAP, CERM, 1 µF, 16 V,+/- 10%, X7R, 0603; Manufacturer: MuRata; Polarized: N; CompType: Capacitor; Value: 1uF; U/M: EA; Cap_F: 0.000001; Tolerance_%: 10; ESR_ohm: 0.011; Value1: 0.011 ohm; VDC_V: 16; Value2: 16V; TaMin_C: -55; TaMax_C: 125; Cap_Case: 0603; SizeArea_mm2: 1.28; SizeAreaWB_mm2: 4.68; SizeX_mm: 1.6; SizeY_mm: 0.8; SizeZ_mm: 1; AEC Category: Q200; Green_Lifecycle: Active; Green_REACh: Passed
signal-integrity model Cap
simulation model Cap
footprint 0603
footprint 0603M
footprint 0603L
footprint 0603_HV
footprint 0603S
pins: 1, 2

## GRM188R71C105KE15D
designator C?  ValueDisplayed: 1µF  (hidden comment: GRM188R71C105KE15D)
CAP, CERM, 1 µF, 16 V,+/- 10%, X7R, 0603; Manufacturer: MuRata; Polarized: N; CompType: Capacitor; Value: 1uF; U/M: EA; Cap_F: 0.000001; Tolerance_%: 10; VDC_V: 16; Value2: 16V; TaMin_C: -55; TaMax_C: 125; Cap_Case: 0603; SizeArea_mm2: 1.28; SizeAreaWB_mm2: 4.68; SizeX_mm: 1.6; SizeY_mm: 0.8; SizeZ_mm: 1; AEC Category: Q200
signal-integrity model Cap
simulation model Cap
footprint 0603
footprint 0603M
footprint 0603L
footprint 0603_HV
footprint 0603S
pins: 1, 2

## GRM188R71C123KA01D
designator C?  ValueDisplayed: 0.012µF  (hidden comment: GRM188R71C123KA01D)
CAP, CERM, 0.012 µF, 16 V,+/- 10%, X7R, 0603; Manufacturer: MuRata; Polarized: N; CompType: Capacitor; Value: 0.012uF; U/M: EA; Cap_F: 0.000000012; Tolerance_%: 10; VDC_V: 16; Value2: 16V; TaMin_C: -55; TaMax_C: 125; Cap_Case: 0603; SizeArea_mm2: 1.28; SizeAreaWB_mm2: 4.68; SizeX_mm: 1.6; SizeY_mm: 0.8; SizeZ_mm: 1; AEC Category: Q200
signal-integrity model Cap
simulation model Cap
footprint 0603
footprint 0603M
footprint 0603L
footprint 0603_HV
footprint 0603S
pins: 1, 2

## GRM188R71C124KA01D
designator C?  ValueDisplayed: 0.12µF  (hidden comment: GRM188R71C124KA01D)
CAP, CERM, 0.12 µF, 16 V,+/- 10%, X7R, 0603; Manufacturer: MuRata; Polarized: N; CompType: Capacitor; Value: 0.12uF; U/M: EA; Cap_F: 0.00000012; Tolerance_%: 10; VDC_V: 16; Value2: 16V; TaMin_C: -55; TaMax_C: 125; Cap_Case: 0603; SizeArea_mm2: 1.28; SizeAreaWB_mm2: 4.68; SizeX_mm: 1.6; SizeY_mm: 0.8; SizeZ_mm: 1; AEC Category: Q200
signal-integrity model Cap
simulation model Cap
footprint 0603
footprint 0603M
footprint 0603L
footprint 0603_HV
footprint 0603S
pins: 1, 2

## GRM188R71C153KA01D
designator C?  ValueDisplayed: 0.015µF  (hidden comment: GRM188R71C153KA01D)
CAP, CERM, 0.015 µF, 16 V,+/- 10%, X7R, 0603; Manufacturer: MuRata; Polarized: N; CompType: Capacitor; Value: 0.015uF; U/M: EA; Cap_F: 0.000000015; Tolerance_%: 10; VDC_V: 16; Value2: 16V; TaMin_C: -55; TaMax_C: 125; Cap_Case: 0603; SizeArea_mm2: 1.28; SizeAreaWB_mm2: 4.68; SizeX_mm: 1.6; SizeY_mm: 0.8; SizeZ_mm: 1; AEC Category: Q200; Green_Lifecycle: Active; Green_REACh: Passed
signal-integrity model Cap
simulation model Cap
footprint 0603
footprint 0603M
footprint 0603L
footprint 0603_HV
footprint 0603S
pins: 1, 2

## GRM188R71C154KA01D
designator C?  ValueDisplayed: 0.15µF  (hidden comment: GRM188R71C154KA01D)
CAP, CERM, 0.15 µF, 16 V,+/- 10%, X7R, 0603; Manufacturer: MuRata; Polarized: N; CompType: Capacitor; Value: 0.15uF; U/M: EA; Cap_F: 0.00000015; Tolerance_%: 10; VDC_V: 16; Value2: 16V; TaMin_C: -55; TaMax_C: 125; Cap_Case: 0603; SizeArea_mm2: 1.28; SizeAreaWB_mm2: 4.68; SizeX_mm: 1.6; SizeY_mm: 0.8; SizeZ_mm: 1; AEC Category: Q200; Green_Lifecycle: Active; Green_REACh: Passed
signal-integrity model Cap
simulation model Cap
footprint 0603
footprint 0603M
footprint 0603L
footprint 0603_HV
footprint 0603S
pins: 1, 2

## GRM188R71C183KA01D
designator C?  ValueDisplayed: 0.018µF  (hidden comment: GRM188R71C183KA01D)
CAP, CERM, 0.018 µF, 16 V,+/- 10%, X7R, 0603; Manufacturer: MuRata; Polarized: N; CompType: Capacitor; Value: 0.018uF; U/M: EA; Cap_F: 0.000000018; Tolerance_%: 10; VDC_V: 16; Value2: 16V; TaMin_C: -55; TaMax_C: 125; Cap_Case: 0603; SizeArea_mm2: 1.28; SizeAreaWB_mm2: 4.68; SizeX_mm: 1.6; SizeY_mm: 0.8; SizeZ_mm: 1; AEC Category: Q200
signal-integrity model Cap
simulation model Cap
footprint 0603
footprint 0603M
footprint 0603L
footprint 0603_HV
footprint 0603S
pins: 1, 2

## GRM188R71C184KA01D
designator C?  ValueDisplayed: 0.18µF  (hidden comment: GRM188R71C184KA01D)
CAP, CERM, 0.18 µF, 16 V,+/- 10%, X7R, 0603; Manufacturer: MuRata; Polarized: N; CompType: Capacitor; Value: 0.18uF; U/M: EA; Cap_F: 0.00000018; Tolerance_%: 10; VDC_V: 16; Value2: 16V; TaMin_C: -55; TaMax_C: 125; Cap_Case: 0603; SizeArea_mm2: 1.28; SizeAreaWB_mm2: 4.68; SizeX_mm: 1.6; SizeY_mm: 0.8; SizeZ_mm: 1; AEC Category: Q200
signal-integrity model Cap
simulation model Cap
footprint 0603
footprint 0603M
footprint 0603L
footprint 0603_HV
footprint 0603S
pins: 1, 2

## GRM188R71C222KA01D
designator C?  ValueDisplayed: 2200pF  (hidden comment: GRM188R71C222KA01D)
CAP, CERM, 2200 pF, 16 V,+/- 10%, X7R, 0603; Manufacturer: MuRata; Polarized: N; CompType: Capacitor; Value: 2200pF; U/M: EA; Cap_F: 0.0000000022; Tolerance_%: 10; VDC_V: 16; Value2: 16V; TaMin_C: -55; TaMax_C: 125; Cap_Case: 0603; SizeArea_mm2: 1.28; SizeAreaWB_mm2: 4.68; SizeX_mm: 1.6; SizeY_mm: 0.8; SizeZ_mm: 1; AEC Category: Q200; Green_Lifecycle: Active; Green_REACh: Passed
signal-integrity model Cap
simulation model Cap
footprint 0603
footprint 0603M
footprint 0603L
footprint 0603_HV
footprint 0603S
pins: 1, 2

## GRM188R71C223KA01D
designator C?  ValueDisplayed: 0.022µF  (hidden comment: GRM188R71C223KA01D)
CAP, CERM, 0.022 µF, 16 V,+/- 10%, X7R, 0603; Manufacturer: MuRata; Polarized: N; CompType: Capacitor; Value: 0.022uF; U/M: EA; Cap_F: 0.000000022; Tolerance_%: 10; VDC_V: 16; Value2: 16V; TaMin_C: -55; TaMax_C: 125; Cap_Case: 0603; SizeArea_mm2: 1.28; SizeAreaWB_mm2: 4.68; SizeX_mm: 1.6; SizeY_mm: 0.8; SizeZ_mm: 1; AEC Category: Q200; Green_Lifecycle: Active; Green_REACh: Passed
signal-integrity model Cap
simulation model Cap
footprint 0603
footprint 0603M
footprint 0603L
footprint 0603_HV
footprint 0603S
pins: 1, 2

## GRM188R71C224KA01D
designator C?  ValueDisplayed: 0.22µF  (hidden comment: GRM188R71C224KA01D)
CAP, CERM, 0.22 µF, 16 V,+/- 10%, X7R, 0603; Manufacturer: MuRata; Polarized: N; CompType: Capacitor; Value: 0.22uF; U/M: EA; Cap_F: 0.00000022; Tolerance_%: 10; VDC_V: 16; Value2: 16V; TaMin_C: -55; TaMax_C: 125; Cap_Case: 0603; SizeArea_mm2: 1.28; SizeAreaWB_mm2: 4.68; SizeX_mm: 1.6; SizeY_mm: 0.8; SizeZ_mm: 1; AEC Category: Q200; Green_Lifecycle: Active; Green_REACh: Passed
signal-integrity model Cap
simulation model Cap
footprint 0603
footprint 0603M
footprint 0603L
footprint 0603_HV
footprint 0603S
pins: 1, 2

## GRM188R71C273KA01D
designator C?  ValueDisplayed: 0.027µF  (hidden comment: GRM188R71C273KA01D)
CAP, CERM, 0.027 µF, 16 V,+/- 10%, X7R, 0603; Manufacturer: MuRata; Polarized: N; CompType: Capacitor; Value: 0.027uF; U/M: EA; Cap_F: 0.000000027; Tolerance_%: 10; VDC_V: 16; Value2: 16V; TaMin_C: -55; TaMax_C: 125; Cap_Case: 0603; SizeArea_mm2: 1.28; SizeAreaWB_mm2: 4.68; SizeX_mm: 1.6; SizeY_mm: 0.8; SizeZ_mm: 1; AEC Category: Q200; Green_Lifecycle: Active; Green_REACh: Passed
signal-integrity model Cap
simulation model Cap
footprint 0603
footprint 0603M
footprint 0603L
footprint 0603_HV
footprint 0603S
pins: 1, 2

## GRM188R71C274KA01D
designator C?  ValueDisplayed: 0.27µF  (hidden comment: GRM188R71C274KA01D)
CAP, CERM, 0.27 µF, 16 V,+/- 10%, X7R, 0603; Manufacturer: MuRata; Polarized: N; CompType: Capacitor; Value: 0.27uF; U/M: EA; Cap_F: 0.00000027; Tolerance_%: 10; VDC_V: 16; Value2: 16V; TaMin_C: -55; TaMax_C: 125; Cap_Case: 0603; SizeArea_mm2: 1.28; SizeAreaWB_mm2: 4.68; SizeX_mm: 1.6; SizeY_mm: 0.8; SizeZ_mm: 1; AEC Category: Q200
signal-integrity model Cap
simulation model Cap
footprint 0603
footprint 0603M
footprint 0603L
footprint 0603_HV
footprint 0603S
pins: 1, 2

## GRM188R71C333KA01D
designator C?  ValueDisplayed: 0.033µF  (hidden comment: GRM188R71C333KA01D)
CAP, CERM, 0.033 µF, 16 V,+/- 10%, X7R, 0603; Manufacturer: MuRata; Polarized: N; CompType: Capacitor; Value: 0.033uF; U/M: EA; Cap_F: 0.000000033; Tolerance_%: 10; VDC_V: 16; Value2: 16V; TaMin_C: -55; TaMax_C: 125; Cap_Case: 0603; SizeArea_mm2: 1.28; SizeAreaWB_mm2: 4.68; SizeX_mm: 1.6; SizeY_mm: 0.8; SizeZ_mm: 1; AEC Category: Q200; Green_Lifecycle: Active; Green_REACh: Passed
signal-integrity model Cap
simulation model Cap
footprint 0603
footprint 0603M
footprint 0603L
footprint 0603_HV
footprint 0603S
pins: 1, 2

## GRM188R71C334KA01D
designator C?  ValueDisplayed: 0.33µF  (hidden comment: GRM188R71C334KA01D)
CAP, CERM, 0.33 µF, 16 V,+/- 10%, X7R, 0603; Manufacturer: MuRata; Polarized: N; CompType: Capacitor; Value: 0.33uF; U/M: EA; Cap_F: 0.00000033; Tolerance_%: 10; VDC_V: 16; Value2: 16V; TaMin_C: -55; TaMax_C: 125; Cap_Case: 0603; SizeArea_mm2: 1.28; SizeAreaWB_mm2: 4.68; SizeX_mm: 1.6; SizeY_mm: 0.8; SizeZ_mm: 1; AEC Category: Q200; Green_Lifecycle: Active; Green_REACh: Passed
signal-integrity model Cap
simulation model Cap
footprint 0603
footprint 0603M
footprint 0603L
footprint 0603_HV
footprint 0603S
pins: 1, 2

## GRM188R71C393KA01D
designator C?  ValueDisplayed: 0.039µF  (hidden comment: GRM188R71C393KA01D)
CAP, CERM, 0.039 µF, 16 V,+/- 10%, X7R, 0603; Manufacturer: MuRata; Polarized: N; CompType: Capacitor; Value: 0.039uF; U/M: EA; Cap_F: 0.000000039; Tolerance_%: 10; VDC_V: 16; Value2: 16V; TaMin_C: -55; TaMax_C: 125; Cap_Case: 0603; SizeArea_mm2: 1.28; SizeAreaWB_mm2: 4.68; SizeX_mm: 1.6; SizeY_mm: 0.8; SizeZ_mm: 1; AEC Category: Q200
signal-integrity model Cap
simulation model Cap
footprint 0603
footprint 0603M
footprint 0603L
footprint 0603_HV
footprint 0603S
pins: 1, 2

## GRM188R71C394KA88D
designator C?  ValueDisplayed: 0.39µF  (hidden comment: GRM188R71C394KA88D)
CAP, CERM, 0.39 µF, 16 V,+/- 10%, X7R, 0603; Manufacturer: MuRata; Polarized: N; CompType: Capacitor; Value: 0.39uF; U/M: EA; Cap_F: 0.00000039; Tolerance_%: 10; VDC_V: 16; Value2: 16V; TaMin_C: -55; TaMax_C: 125; Cap_Case: 0603; SizeArea_mm2: 1.28; SizeAreaWB_mm2: 4.68; SizeX_mm: 1.6; SizeY_mm: 0.8; SizeZ_mm: 1; AEC Category: Q200; Green_Lifecycle: Active; Green_REACh: Passed
signal-integrity model Cap
simulation model Cap
footprint 0603
footprint 0603M
footprint 0603L
footprint 0603_HV
footprint 0603S
pins: 1, 2

## GRM188R71C472KA01D
designator C?  ValueDisplayed: 4700pF  (hidden comment: GRM188R71C472KA01D)
CAP, CERM, 4700 pF, 16 V,+/- 10%, X7R, 0603; Manufacturer: MuRata; Polarized: N; CompType: Capacitor; Value: 4700pF; U/M: EA; Cap_F: 0.0000000047; Tolerance_%: 10; VDC_V: 16; Value2: 16V; TaMin_C: -55; TaMax_C: 125; Cap_Case: 0603; SizeArea_mm2: 1.28; SizeAreaWB_mm2: 4.68; SizeX_mm: 1.6; SizeY_mm: 0.8; SizeZ_mm: 1; AEC Category: Q200; Green_Lifecycle: Active; Green_REACh: Passed
signal-integrity model Cap
simulation model Cap
footprint 0603
footprint 0603M
footprint 0603L
footprint 0603_HV
footprint 0603S
pins: 1, 2

## GRM188R71C473KA01D
designator C?  ValueDisplayed: 0.047µF  (hidden comment: GRM188R71C473KA01D)
CAP, CERM, 0.047 µF, 16 V,+/- 10%, X7R, 0603; Manufacturer: MuRata; Polarized: N; CompType: Capacitor; Value: 0.047uF; U/M: EA; Cap_F: 0.000000047; Tolerance_%: 10; VDC_V: 16; Value2: 16V; TaMin_C: -55; TaMax_C: 125; Cap_Case: 0603; SizeArea_mm2: 1.28; SizeAreaWB_mm2: 4.68; SizeX_mm: 1.6; SizeY_mm: 0.8; SizeZ_mm: 1; AEC Category: Q200; Green_Lifecycle: Active; Green_REACh: Passed
signal-integrity model Cap
simulation model Cap
footprint 0603
footprint 0603M
footprint 0603L
footprint 0603_HV
footprint 0603S
pins: 1, 2

## GRM188R71C474KA88D
designator C?  ValueDisplayed: 0.47µF  (hidden comment: GRM188R71C474KA88D)
CAP, CERM, 0.47 µF, 16 V,+/- 10%, X7R, 0603; Manufacturer: MuRata; Polarized: N; CompType: Capacitor; Value: 0.47uF; U/M: EA; Cap_F: 0.00000047; Tolerance_%: 10; VDC_V: 16; Value2: 16V; TaMin_C: -55; TaMax_C: 125; Cap_Case: 0603; SizeArea_mm2: 1.28; SizeAreaWB_mm2: 4.68; SizeX_mm: 1.6; SizeY_mm: 0.8; SizeZ_mm: 1; AEC Category: Q200; Green_Lifecycle: Active; Green_REACh: Passed
signal-integrity model Cap
simulation model Cap
footprint 0603
footprint 0603M
footprint 0603L
footprint 0603_HV
footprint 0603S
pins: 1, 2

## GRM188R71C563KA01D
designator C?  ValueDisplayed: 0.056µF  (hidden comment: GRM188R71C563KA01D)
CAP, CERM, 0.056 µF, 16 V,+/- 10%, X7R, 0603; Manufacturer: MuRata; Polarized: N; CompType: Capacitor; Value: 0.056uF; U/M: EA; Cap_F: 0.000000056; Tolerance_%: 10; VDC_V: 16; Value2: 16V; TaMin_C: -55; TaMax_C: 125; Cap_Case: 0603; SizeArea_mm2: 1.28; SizeAreaWB_mm2: 4.68; SizeX_mm: 1.6; SizeY_mm: 0.8; SizeZ_mm: 1; AEC Category: Q200; Green_Lifecycle: Active; Green_REACh: Passed
signal-integrity model Cap
simulation model Cap
footprint 0603
footprint 0603M
footprint 0603L
footprint 0603_HV
footprint 0603S
pins: 1, 2

## GRM188R71C683KA01D
designator C?  ValueDisplayed: 0.068µF  (hidden comment: GRM188R71C683KA01D)
CAP, CERM, 0.068 µF, 16 V,+/- 10%, X7R, 0603; Manufacturer: MuRata; Polarized: N; CompType: Capacitor; Value: 0.068uF; U/M: EA; Cap_F: 0.000000068; Tolerance_%: 10; VDC_V: 16; Value2: 16V; TaMin_C: -55; TaMax_C: 125; Cap_Case: 0603; SizeArea_mm2: 1.28; SizeAreaWB_mm2: 4.68; SizeX_mm: 1.6; SizeY_mm: 0.8; SizeZ_mm: 1; AEC Category: Q200
signal-integrity model Cap
simulation model Cap
footprint 0603
footprint 0603M
footprint 0603L
footprint 0603_HV
footprint 0603S
pins: 1, 2

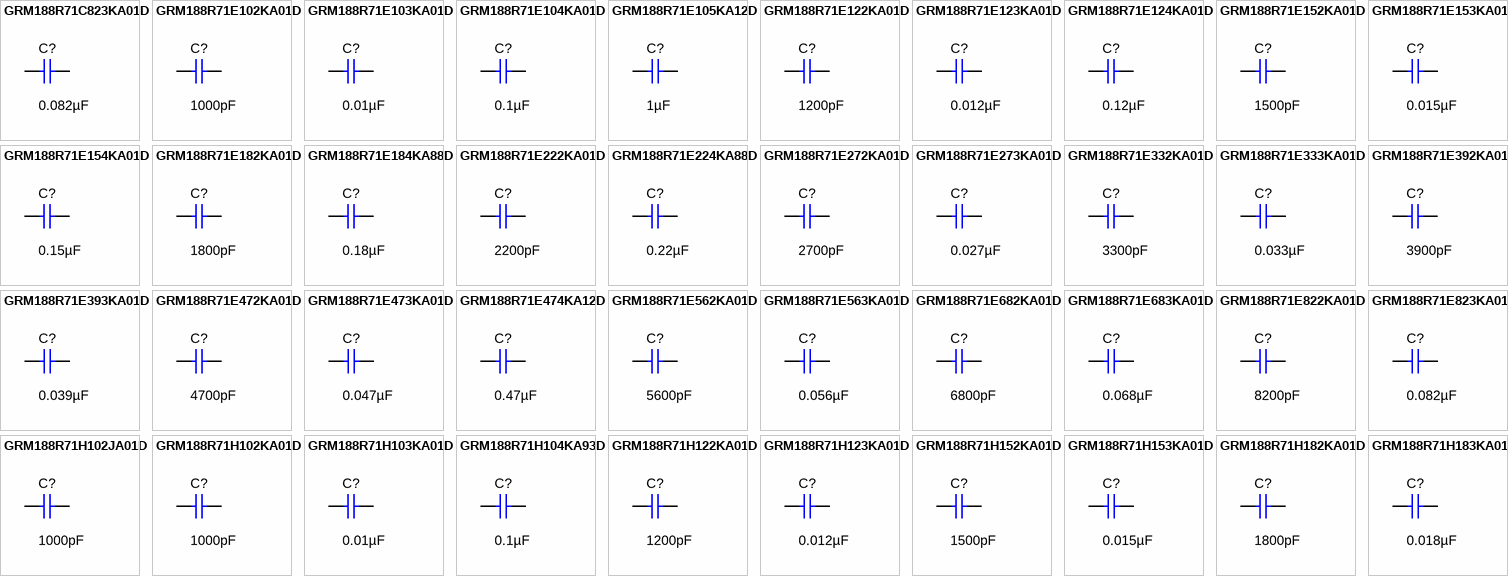
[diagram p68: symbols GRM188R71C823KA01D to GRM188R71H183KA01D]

## GRM188R71C823KA01D
designator C?  ValueDisplayed: 0.082µF  (hidden comment: GRM188R71C823KA01D)
CAP, CERM, 0.082 µF, 16 V,+/- 10%, X7R, 0603; Manufacturer: MuRata; Polarized: N; CompType: Capacitor; Value: 0.082uF; U/M: EA; Cap_F: 0.000000082; Tolerance_%: 10; VDC_V: 16; Value2: 16V; TaMin_C: -55; TaMax_C: 125; Cap_Case: 0603; SizeArea_mm2: 1.28; SizeAreaWB_mm2: 4.68; SizeX_mm: 1.6; SizeY_mm: 0.8; SizeZ_mm: 1; AEC Category: Q200; Green_Lifecycle: Active; Green_REACh: Passed
signal-integrity model Cap
simulation model Cap
footprint 0603
footprint 0603M
footprint 0603L
footprint 0603_HV
footprint 0603S
pins: 1, 2

## GRM188R71E102KA01D
designator C?  ValueDisplayed: 1000pF  (hidden comment: GRM188R71E102KA01D)
CAP, CERM, 1000 pF, 25 V,+/- 10%, X7R, 0603; Manufacturer: MuRata; Polarized: N; CompType: Capacitor; Value: 1000pF; U/M: EA; Cap_F: 0.000000001; Tolerance_%: 10; VDC_V: 25; Value2: 25V; TaMin_C: -55; TaMax_C: 125; Cap_Case: 0603; SizeArea_mm2: 1.28; SizeAreaWB_mm2: 4.68; SizeX_mm: 1.6; SizeY_mm: 0.8; SizeZ_mm: 1; AEC Category: Q200; Green_Lifecycle: Active; Green_REACh: Passed
signal-integrity model Cap
simulation model Cap
footprint 0603
footprint 0603M
footprint 0603L
footprint 0603_HV
footprint 0603S
pins: 1, 2

## GRM188R71E103KA01D
designator C?  ValueDisplayed: 0.01µF  (hidden comment: GRM188R71E103KA01D)
CAP, CERM, 0.01 µF, 25 V,+/- 10%, X7R, 0603; Manufacturer: MuRata; Polarized: N; CompType: Capacitor; Value: 0.01uF; U/M: EA; Cap_F: 0.00000001; Tolerance_%: 10; VDC_V: 25; Value2: 25V; TaMin_C: -55; TaMax_C: 125; Cap_Case: 0603; SizeArea_mm2: 1.28; SizeAreaWB_mm2: 4.68; SizeX_mm: 1.6; SizeY_mm: 0.8; SizeZ_mm: 1; AEC Category: Q200; Green_Lifecycle: Active; Green_REACh: Passed
signal-integrity model Cap
simulation model Cap
footprint 0603
footprint 0603M
footprint 0603L
footprint 0603_HV
footprint 0603S
pins: 1, 2

## GRM188R71E104KA01D
designator C?  ValueDisplayed: 0.1µF  (hidden comment: GRM188R71E104KA01D)
CAP, CERM, 0.1 µF, 25 V,+/- 10%, X7R, 0603; Manufacturer: MuRata; Polarized: N; CompType: Capacitor; Value: 0.1uF; U/M: EA; Cap_F: 0.0000001; Tolerance_%: 10; VDC_V: 25; Value2: 25V; TaMin_C: -55; TaMax_C: 125; Cap_Case: 0603; SizeArea_mm2: 1.28; SizeAreaWB_mm2: 4.68; SizeX_mm: 1.6; SizeY_mm: 0.8; SizeZ_mm: 1; AEC Category: Q200; Green_Lifecycle: Active; Green_REACh: Passed
signal-integrity model Cap
simulation model Cap
footprint 0603
footprint 0603M
footprint 0603L
footprint 0603_HV
footprint 0603S
pins: 1, 2

## GRM188R71E105KA12D
designator C?  ValueDisplayed: 1µF  (hidden comment: GRM188R71E105KA12D)
CAP, CERM, 1 µF, 25 V,+/- 10%, X7R, 0603; Manufacturer: MuRata; Polarized: N; CompType: Capacitor; Value: 1uF; U/M: EA; Cap_F: 0.000001; Tolerance_%: 10; VDC_V: 25; Value2: 25V; TaMin_C: -55; TaMax_C: 125; Cap_Case: 0603; SizeArea_mm2: 1.28; SizeAreaWB_mm2: 4.68; SizeX_mm: 1.6; SizeY_mm: 0.8; SizeZ_mm: 1; AEC Category: Q200; Green_Lifecycle: Active; Green_REACh: Passed
signal-integrity model Cap
simulation model Cap
footprint 0603
footprint 0603M
footprint 0603L
footprint 0603_HV
footprint 0603S
pins: 1, 2

## GRM188R71E122KA01D
designator C?  ValueDisplayed: 1200pF  (hidden comment: GRM188R71E122KA01D)
CAP, CERM, 1200 pF, 25 V,+/- 10%, X7R, 0603; Manufacturer: MuRata; Polarized: N; CompType: Capacitor; Value: 1200pF; U/M: EA; Cap_F: 0.0000000012; Tolerance_%: 10; VDC_V: 25; Value2: 25V; TaMin_C: -55; TaMax_C: 125; Cap_Case: 0603; SizeArea_mm2: 1.28; SizeAreaWB_mm2: 4.68; SizeX_mm: 1.6; SizeY_mm: 0.8; SizeZ_mm: 1; AEC Category: Q200
signal-integrity model Cap
simulation model Cap
footprint 0603
footprint 0603M
footprint 0603L
footprint 0603_HV
footprint 0603S
pins: 1, 2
